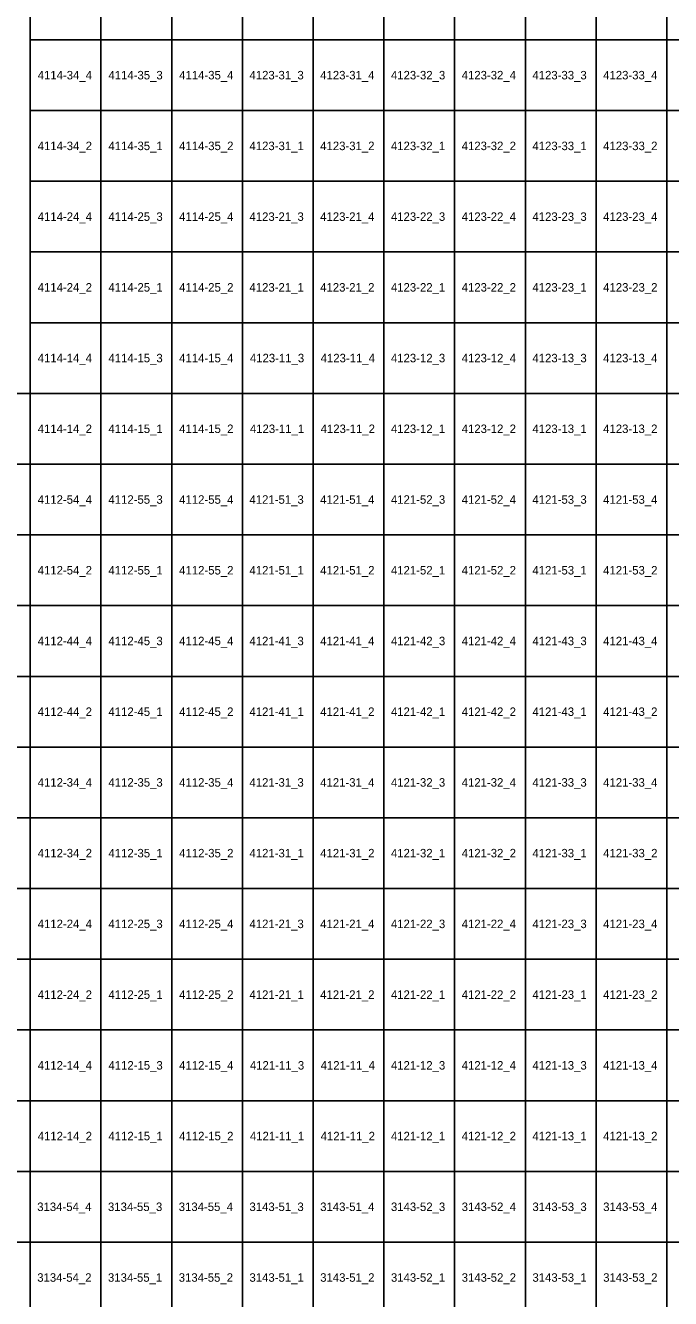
# Model space of a CAD drawing. Extents: x 312500 to 765000, y 172500 to 440000.
# Drawn here: x 342332 to 365129, y 295507 to 340507 of the extents above; entities that cross this region are included whole.
import ezdxf

# ---------------------------------------------------------------- set-up
doc = ezdxf.new("R2010")
doc.units = 0
doc.layers.add('Topo5_ramis_TKS2025', color=7, linetype='Continuous')
doc.layers.add('Topo5_ramis_TKS2025_Nr', color=7, linetype='Continuous')

msp = doc.modelspace()

# ---------------------------------------------------------------- linework, layer by layer
at = {"layer": 'Topo5_ramis_TKS2025'}
for points in [[(342500, 340000), (342500, 342500), (345000, 342500), (345000, 340000), (342500, 340000)], [(345000, 340000), (345000, 342500), (347500, 342500), (347500, 340000), (345000, 340000)], [(347500, 340000), (347500, 342500), (350000, 342500), (350000, 340000), (347500, 340000)], [(350000, 340000), (350000, 342500), (352500, 342500), (352500, 340000), (350000, 340000)], [(352500, 340000), (352500, 342500), (355000, 342500), (355000, 340000), (352500, 340000)], [(355000, 340000), (355000, 342500), (357500, 342500), (357500, 340000), (355000, 340000)], [(357500, 340000), (357500, 342500), (360000, 342500), (360000, 340000), (357500, 340000)], [(360000, 340000), (360000, 342500), (362500, 342500), (362500, 340000), (360000, 340000)], [(362500, 340000), (362500, 342500), (365000, 342500), (365000, 340000), (362500, 340000)], [(365000, 340000), (365000, 342500), (367500, 342500), (367500, 340000), (365000, 340000)], [(342500, 337500), (342500, 340000), (345000, 340000), (345000, 337500), (342500, 337500)], [(345000, 337500), (345000, 340000), (347500, 340000), (347500, 337500), (345000, 337500)], [(347500, 337500), (347500, 340000), (350000, 340000), (350000, 337500), (347500, 337500)], [(350000, 337500), (350000, 340000), (352500, 340000), (352500, 337500), (350000, 337500)], [(352500, 337500), (352500, 340000), (355000, 340000), (355000, 337500), (352500, 337500)], [(355000, 337500), (355000, 340000), (357500, 340000), (357500, 337500), (355000, 337500)], [(357500, 337500), (357500, 340000), (360000, 340000), (360000, 337500), (357500, 337500)], [(360000, 337500), (360000, 340000), (362500, 340000), (362500, 337500), (360000, 337500)], [(362500, 337500), (362500, 340000), (365000, 340000), (365000, 337500), (362500, 337500)], [(365000, 337500), (365000, 340000), (367500, 340000), (367500, 337500), (365000, 337500)], [(342500, 335000), (342500, 337500), (345000, 337500), (345000, 335000), (342500, 335000)], [(345000, 335000), (345000, 337500), (347500, 337500), (347500, 335000), (345000, 335000)], [(347500, 335000), (347500, 337500), (350000, 337500), (350000, 335000), (347500, 335000)], [(350000, 335000), (350000, 337500), (352500, 337500), (352500, 335000), (350000, 335000)], [(352500, 335000), (352500, 337500), (355000, 337500), (355000, 335000), (352500, 335000)], [(355000, 335000), (355000, 337500), (357500, 337500), (357500, 335000), (355000, 335000)], [(357500, 335000), (357500, 337500), (360000, 337500), (360000, 335000), (357500, 335000)], [(360000, 335000), (360000, 337500), (362500, 337500), (362500, 335000), (360000, 335000)], [(362500, 335000), (362500, 337500), (365000, 337500), (365000, 335000), (362500, 335000)], [(365000, 335000), (365000, 337500), (367500, 337500), (367500, 335000), (365000, 335000)], [(342500, 332500), (342500, 335000), (345000, 335000), (345000, 332500), (342500, 332500)], [(345000, 332500), (345000, 335000), (347500, 335000), (347500, 332500), (345000, 332500)], [(347500, 332500), (347500, 335000), (350000, 335000), (350000, 332500), (347500, 332500)], [(350000, 332500), (350000, 335000), (352500, 335000), (352500, 332500), (350000, 332500)], [(352500, 332500), (352500, 335000), (355000, 335000), (355000, 332500), (352500, 332500)], [(355000, 332500), (355000, 335000), (357500, 335000), (357500, 332500), (355000, 332500)], [(357500, 332500), (357500, 335000), (360000, 335000), (360000, 332500), (357500, 332500)], [(360000, 332500), (360000, 335000), (362500, 335000), (362500, 332500), (360000, 332500)], [(362500, 332500), (362500, 335000), (365000, 335000), (365000, 332500), (362500, 332500)], [(365000, 332500), (365000, 335000), (367500, 335000), (367500, 332500), (365000, 332500)], [(342500, 330000), (342500, 332500), (345000, 332500), (345000, 330000), (342500, 330000)], [(345000, 330000), (345000, 332500), (347500, 332500), (347500, 330000), (345000, 330000)], [(347500, 330000), (347500, 332500), (350000, 332500), (350000, 330000), (347500, 330000)], [(350000, 330000), (350000, 332500), (352500, 332500), (352500, 330000), (350000, 330000)], [(352500, 330000), (352500, 332500), (355000, 332500), (355000, 330000), (352500, 330000)], [(355000, 330000), (355000, 332500), (357500, 332500), (357500, 330000), (355000, 330000)], [(357500, 330000), (357500, 332500), (360000, 332500), (360000, 330000), (357500, 330000)], [(360000, 330000), (360000, 332500), (362500, 332500), (362500, 330000), (360000, 330000)], [(362500, 330000), (362500, 332500), (365000, 332500), (365000, 330000), (362500, 330000)], [(365000, 330000), (365000, 332500), (367500, 332500), (367500, 330000), (365000, 330000)], [(342500, 327500), (342500, 330000), (345000, 330000), (345000, 327500), (342500, 327500)], [(345000, 327500), (345000, 330000), (347500, 330000), (347500, 327500), (345000, 327500)], [(347500, 327500), (347500, 330000), (350000, 330000), (350000, 327500), (347500, 327500)], [(350000, 327500), (350000, 330000), (352500, 330000), (352500, 327500), (350000, 327500)], [(352500, 327500), (352500, 330000), (355000, 330000), (355000, 327500), (352500, 327500)], [(355000, 327500), (355000, 330000), (357500, 330000), (357500, 327500), (355000, 327500)], [(357500, 327500), (357500, 330000), (360000, 330000), (360000, 327500), (357500, 327500)], [(360000, 327500), (360000, 330000), (362500, 330000), (362500, 327500), (360000, 327500)], [(362500, 327500), (362500, 330000), (365000, 330000), (365000, 327500), (362500, 327500)], [(365000, 327500), (365000, 330000), (367500, 330000), (367500, 327500), (365000, 327500)], [(340000, 325000), (340000, 327500), (342500, 327500), (342500, 325000), (340000, 325000)], [(342500, 325000), (342500, 327500), (345000, 327500), (345000, 325000), (342500, 325000)], [(345000, 325000), (345000, 327500), (347500, 327500), (347500, 325000), (345000, 325000)], [(347500, 325000), (347500, 327500), (350000, 327500), (350000, 325000), (347500, 325000)], [(350000, 325000), (350000, 327500), (352500, 327500), (352500, 325000), (350000, 325000)], [(352500, 325000), (352500, 327500), (355000, 327500), (355000, 325000), (352500, 325000)], [(355000, 325000), (355000, 327500), (357500, 327500), (357500, 325000), (355000, 325000)], [(357500, 325000), (357500, 327500), (360000, 327500), (360000, 325000), (357500, 325000)], [(360000, 325000), (360000, 327500), (362500, 327500), (362500, 325000), (360000, 325000)], [(362500, 325000), (362500, 327500), (365000, 327500), (365000, 325000), (362500, 325000)], [(365000, 325000), (365000, 327500), (367500, 327500), (367500, 325000), (365000, 325000)], [(340000, 322500), (340000, 325000), (342500, 325000), (342500, 322500), (340000, 322500)], [(342500, 322500), (342500, 325000), (345000, 325000), (345000, 322500), (342500, 322500)], [(345000, 322500), (345000, 325000), (347500, 325000), (347500, 322500), (345000, 322500)], [(347500, 322500), (347500, 325000), (350000, 325000), (350000, 322500), (347500, 322500)], [(350000, 322500), (350000, 325000), (352500, 325000), (352500, 322500), (350000, 322500)], [(352500, 322500), (352500, 325000), (355000, 325000), (355000, 322500), (352500, 322500)], [(355000, 322500), (355000, 325000), (357500, 325000), (357500, 322500), (355000, 322500)], [(357500, 322500), (357500, 325000), (360000, 325000), (360000, 322500), (357500, 322500)], [(360000, 322500), (360000, 325000), (362500, 325000), (362500, 322500), (360000, 322500)], [(362500, 322500), (362500, 325000), (365000, 325000), (365000, 322500), (362500, 322500)], [(365000, 322500), (365000, 325000), (367500, 325000), (367500, 322500), (365000, 322500)], [(340000, 320000), (340000, 322500), (342500, 322500), (342500, 320000), (340000, 320000)], [(342500, 320000), (342500, 322500), (345000, 322500), (345000, 320000), (342500, 320000)], [(345000, 320000), (345000, 322500), (347500, 322500), (347500, 320000), (345000, 320000)], [(347500, 320000), (347500, 322500), (350000, 322500), (350000, 320000), (347500, 320000)], [(350000, 320000), (350000, 322500), (352500, 322500), (352500, 320000), (350000, 320000)], [(352500, 320000), (352500, 322500), (355000, 322500), (355000, 320000), (352500, 320000)], [(355000, 320000), (355000, 322500), (357500, 322500), (357500, 320000), (355000, 320000)], [(357500, 320000), (357500, 322500), (360000, 322500), (360000, 320000), (357500, 320000)], [(360000, 320000), (360000, 322500), (362500, 322500), (362500, 320000), (360000, 320000)], [(362500, 320000), (362500, 322500), (365000, 322500), (365000, 320000), (362500, 320000)], [(365000, 320000), (365000, 322500), (367500, 322500), (367500, 320000), (365000, 320000)], [(340000, 317500), (340000, 320000), (342500, 320000), (342500, 317500), (340000, 317500)], [(342500, 317500), (342500, 320000), (345000, 320000), (345000, 317500), (342500, 317500)], [(345000, 317500), (345000, 320000), (347500, 320000), (347500, 317500), (345000, 317500)], [(347500, 317500), (347500, 320000), (350000, 320000), (350000, 317500), (347500, 317500)], [(350000, 317500), (350000, 320000), (352500, 320000), (352500, 317500), (350000, 317500)], [(352500, 317500), (352500, 320000), (355000, 320000), (355000, 317500), (352500, 317500)], [(355000, 317500), (355000, 320000), (357500, 320000), (357500, 317500), (355000, 317500)], [(357500, 317500), (357500, 320000), (360000, 320000), (360000, 317500), (357500, 317500)], [(360000, 317500), (360000, 320000), (362500, 320000), (362500, 317500), (360000, 317500)], [(362500, 317500), (362500, 320000), (365000, 320000), (365000, 317500), (362500, 317500)], [(365000, 317500), (365000, 320000), (367500, 320000), (367500, 317500), (365000, 317500)], [(340000, 315000), (340000, 317500), (342500, 317500), (342500, 315000), (340000, 315000)], [(342500, 315000), (342500, 317500), (345000, 317500), (345000, 315000), (342500, 315000)], [(345000, 315000), (345000, 317500), (347500, 317500), (347500, 315000), (345000, 315000)], [(347500, 315000), (347500, 317500), (350000, 317500), (350000, 315000), (347500, 315000)], [(350000, 315000), (350000, 317500), (352500, 317500), (352500, 315000), (350000, 315000)], [(352500, 315000), (352500, 317500), (355000, 317500), (355000, 315000), (352500, 315000)], [(355000, 315000), (355000, 317500), (357500, 317500), (357500, 315000), (355000, 315000)], [(357500, 315000), (357500, 317500), (360000, 317500), (360000, 315000), (357500, 315000)], [(360000, 315000), (360000, 317500), (362500, 317500), (362500, 315000), (360000, 315000)], [(362500, 315000), (362500, 317500), (365000, 317500), (365000, 315000), (362500, 315000)], [(365000, 315000), (365000, 317500), (367500, 317500), (367500, 315000), (365000, 315000)], [(340000, 312500), (340000, 315000), (342500, 315000), (342500, 312500), (340000, 312500)], [(342500, 312500), (342500, 315000), (345000, 315000), (345000, 312500), (342500, 312500)], [(345000, 312500), (345000, 315000), (347500, 315000), (347500, 312500), (345000, 312500)], [(347500, 312500), (347500, 315000), (350000, 315000), (350000, 312500), (347500, 312500)], [(350000, 312500), (350000, 315000), (352500, 315000), (352500, 312500), (350000, 312500)], [(352500, 312500), (352500, 315000), (355000, 315000), (355000, 312500), (352500, 312500)], [(355000, 312500), (355000, 315000), (357500, 315000), (357500, 312500), (355000, 312500)], [(357500, 312500), (357500, 315000), (360000, 315000), (360000, 312500), (357500, 312500)], [(360000, 312500), (360000, 315000), (362500, 315000), (362500, 312500), (360000, 312500)], [(362500, 312500), (362500, 315000), (365000, 315000), (365000, 312500), (362500, 312500)], [(365000, 312500), (365000, 315000), (367500, 315000), (367500, 312500), (365000, 312500)], [(340000, 310000), (340000, 312500), (342500, 312500), (342500, 310000), (340000, 310000)], [(342500, 310000), (342500, 312500), (345000, 312500), (345000, 310000), (342500, 310000)], [(345000, 310000), (345000, 312500), (347500, 312500), (347500, 310000), (345000, 310000)], [(347500, 310000), (347500, 312500), (350000, 312500), (350000, 310000), (347500, 310000)], [(350000, 310000), (350000, 312500), (352500, 312500), (352500, 310000), (350000, 310000)], [(352500, 310000), (352500, 312500), (355000, 312500), (355000, 310000), (352500, 310000)], [(355000, 310000), (355000, 312500), (357500, 312500), (357500, 310000), (355000, 310000)], [(357500, 310000), (357500, 312500), (360000, 312500), (360000, 310000), (357500, 310000)], [(360000, 310000), (360000, 312500), (362500, 312500), (362500, 310000), (360000, 310000)], [(362500, 310000), (362500, 312500), (365000, 312500), (365000, 310000), (362500, 310000)], [(365000, 310000), (365000, 312500), (367500, 312500), (367500, 310000), (365000, 310000)], [(340000, 307500), (340000, 310000), (342500, 310000), (342500, 307500), (340000, 307500)], [(342500, 307500), (342500, 310000), (345000, 310000), (345000, 307500), (342500, 307500)], [(345000, 307500), (345000, 310000), (347500, 310000), (347500, 307500), (345000, 307500)], [(347500, 307500), (347500, 310000), (350000, 310000), (350000, 307500), (347500, 307500)], [(350000, 307500), (350000, 310000), (352500, 310000), (352500, 307500), (350000, 307500)], [(352500, 307500), (352500, 310000), (355000, 310000), (355000, 307500), (352500, 307500)], [(355000, 307500), (355000, 310000), (357500, 310000), (357500, 307500), (355000, 307500)], [(357500, 307500), (357500, 310000), (360000, 310000), (360000, 307500), (357500, 307500)], [(360000, 307500), (360000, 310000), (362500, 310000), (362500, 307500), (360000, 307500)], [(362500, 307500), (362500, 310000), (365000, 310000), (365000, 307500), (362500, 307500)], [(365000, 307500), (365000, 310000), (367500, 310000), (367500, 307500), (365000, 307500)], [(340000, 305000), (340000, 307500), (342500, 307500), (342500, 305000), (340000, 305000)], [(342500, 305000), (342500, 307500), (345000, 307500), (345000, 305000), (342500, 305000)], [(345000, 305000), (345000, 307500), (347500, 307500), (347500, 305000), (345000, 305000)], [(347500, 305000), (347500, 307500), (350000, 307500), (350000, 305000), (347500, 305000)], [(350000, 305000), (350000, 307500), (352500, 307500), (352500, 305000), (350000, 305000)], [(352500, 305000), (352500, 307500), (355000, 307500), (355000, 305000), (352500, 305000)], [(355000, 305000), (355000, 307500), (357500, 307500), (357500, 305000), (355000, 305000)], [(357500, 305000), (357500, 307500), (360000, 307500), (360000, 305000), (357500, 305000)], [(360000, 305000), (360000, 307500), (362500, 307500), (362500, 305000), (360000, 305000)], [(362500, 305000), (362500, 307500), (365000, 307500), (365000, 305000), (362500, 305000)], [(365000, 305000), (365000, 307500), (367500, 307500), (367500, 305000), (365000, 305000)], [(340000, 302500), (340000, 305000), (342500, 305000), (342500, 302500), (340000, 302500)], [(342500, 302500), (342500, 305000), (345000, 305000), (345000, 302500), (342500, 302500)], [(345000, 302500), (345000, 305000), (347500, 305000), (347500, 302500), (345000, 302500)], [(347500, 302500), (347500, 305000), (350000, 305000), (350000, 302500), (347500, 302500)], [(350000, 302500), (350000, 305000), (352500, 305000), (352500, 302500), (350000, 302500)], [(352500, 302500), (352500, 305000), (355000, 305000), (355000, 302500), (352500, 302500)], [(355000, 302500), (355000, 305000), (357500, 305000), (357500, 302500), (355000, 302500)], [(357500, 302500), (357500, 305000), (360000, 305000), (360000, 302500), (357500, 302500)], [(360000, 302500), (360000, 305000), (362500, 305000), (362500, 302500), (360000, 302500)], [(362500, 302500), (362500, 305000), (365000, 305000), (365000, 302500), (362500, 302500)], [(365000, 302500), (365000, 305000), (367500, 305000), (367500, 302500), (365000, 302500)], [(340000, 300000), (340000, 302500), (342500, 302500), (342500, 300000), (340000, 300000)], [(342500, 300000), (342500, 302500), (345000, 302500), (345000, 300000), (342500, 300000)], [(345000, 300000), (345000, 302500), (347500, 302500), (347500, 300000), (345000, 300000)], [(347500, 300000), (347500, 302500), (350000, 302500), (350000, 300000), (347500, 300000)], [(350000, 300000), (350000, 302500), (352500, 302500), (352500, 300000), (350000, 300000)], [(352500, 300000), (352500, 302500), (355000, 302500), (355000, 300000), (352500, 300000)], [(355000, 300000), (355000, 302500), (357500, 302500), (357500, 300000), (355000, 300000)], [(357500, 300000), (357500, 302500), (360000, 302500), (360000, 300000), (357500, 300000)], [(360000, 300000), (360000, 302500), (362500, 302500), (362500, 300000), (360000, 300000)], [(362500, 300000), (362500, 302500), (365000, 302500), (365000, 300000), (362500, 300000)], [(365000, 300000), (365000, 302500), (367500, 302500), (367500, 300000), (365000, 300000)], [(340000, 297500), (340000, 300000), (342500, 300000), (342500, 297500), (340000, 297500)], [(342500, 297500), (342500, 300000), (345000, 300000), (345000, 297500), (342500, 297500)], [(345000, 297500), (345000, 300000), (347500, 300000), (347500, 297500), (345000, 297500)], [(347500, 297500), (347500, 300000), (350000, 300000), (350000, 297500), (347500, 297500)], [(350000, 297500), (350000, 300000), (352500, 300000), (352500, 297500), (350000, 297500)], [(352500, 297500), (352500, 300000), (355000, 300000), (355000, 297500), (352500, 297500)], [(355000, 297500), (355000, 300000), (357500, 300000), (357500, 297500), (355000, 297500)], [(357500, 297500), (357500, 300000), (360000, 300000), (360000, 297500), (357500, 297500)], [(360000, 297500), (360000, 300000), (362500, 300000), (362500, 297500), (360000, 297500)], [(362500, 297500), (362500, 300000), (365000, 300000), (365000, 297500), (362500, 297500)], [(365000, 297500), (365000, 300000), (367500, 300000), (367500, 297500), (365000, 297500)], [(340000, 295000), (340000, 297500), (342500, 297500), (342500, 295000), (340000, 295000)], [(342500, 295000), (342500, 297500), (345000, 297500), (345000, 295000), (342500, 295000)], [(345000, 295000), (345000, 297500), (347500, 297500), (347500, 295000), (345000, 295000)], [(347500, 295000), (347500, 297500), (350000, 297500), (350000, 295000), (347500, 295000)], [(350000, 295000), (350000, 297500), (352500, 297500), (352500, 295000), (350000, 295000)], [(352500, 295000), (352500, 297500), (355000, 297500), (355000, 295000), (352500, 295000)], [(355000, 295000), (355000, 297500), (357500, 297500), (357500, 295000), (355000, 295000)], [(357500, 295000), (357500, 297500), (360000, 297500), (360000, 295000), (357500, 295000)], [(360000, 295000), (360000, 297500), (362500, 297500), (362500, 295000), (360000, 295000)], [(362500, 295000), (362500, 297500), (365000, 297500), (365000, 295000), (362500, 295000)], [(365000, 295000), (365000, 297500), (367500, 297500), (367500, 295000), (365000, 295000)]]:
    msp.add_lwpolyline(points, dxfattribs=at)

# ---------------------------------------------------------------- texts
at = {"layer": 'Topo5_ramis_TKS2025_Nr'}
for s, p in [('4114-34_4', (342764, 338600)), ('4114-35_3', (345264, 338600)), ('4114-35_4', (347764, 338600)), ('4123-31_3', (350248, 338600)), ('4123-31_4', (352748, 338600)), ('4123-32_3', (355248, 338600)), ('4123-32_4', (357748, 338600)), ('4123-33_3', (360248, 338600)), ('4123-33_4', (362748, 338600)), ('4114-34_2', (342764, 336100)), ('4114-35_1', (345264, 336100)), ('4114-35_2', (347764, 336100)), ('4123-31_1', (350248, 336100)), ('4123-31_2', (352748, 336100)), ('4123-32_1', (355248, 336100)), ('4123-32_2', (357748, 336100)), ('4123-33_1', (360248, 336100)), ('4123-33_2', (362748, 336100)), ('4114-24_4', (342764, 333600)), ('4114-25_3', (345264, 333600)), ('4114-25_4', (347764, 333600)), ('4123-21_3', (350248, 333600)), ('4123-21_4', (352748, 333600)), ('4123-22_3', (355248, 333600)), ('4123-22_4', (357748, 333600)), ('4123-23_3', (360248, 333600)), ('4123-23_4', (362748, 333600)), ('4114-24_2', (342764, 331100)), ('4114-25_1', (345264, 331100)), ('4114-25_2', (347764, 331100)), ('4123-21_1', (350248, 331100)), ('4123-21_2', (352748, 331100)), ('4123-22_1', (355248, 331100)), ('4123-22_2', (357748, 331100)), ('4123-23_1', (360248, 331100)), ('4123-23_2', (362748, 331100)), ('4114-14_4', (342764, 328600)), ('4114-15_3', (345264, 328600)), ('4114-15_4', (347764, 328600)), ('4123-11_3', (350264, 328600)), ('4123-11_4', (352764, 328600)), ('4123-12_3', (355248, 328600)), ('4123-12_4', (357748, 328600)), ('4123-13_3', (360248, 328600)), ('4123-13_4', (362748, 328600)), ('4114-14_2', (342764, 326100)), ('4114-15_1', (345264, 326100)), ('4114-15_2', (347764, 326100)), ('4123-11_1', (350264, 326100)), ('4123-11_2', (352764, 326100)), ('4123-12_1', (355248, 326100)), ('4123-12_2', (357748, 326100)), ('4123-13_1', (360248, 326100)), ('4123-13_2', (362748, 326100)), ('4112-54_4', (342764, 323600)), ('4112-55_3', (345264, 323600)), ('4112-55_4', (347764, 323600)), ('4121-51_3', (350248, 323600)), ('4121-51_4', (352748, 323600)), ('4121-52_3', (355248, 323600)), ('4121-52_4', (357748, 323600)), ('4121-53_3', (360248, 323600)), ('4121-53_4', (362748, 323600)), ('4112-54_2', (342764, 321100)), ('4112-55_1', (345264, 321100)), ('4112-55_2', (347764, 321100)), ('4121-51_1', (350248, 321100)), ('4121-51_2', (352748, 321100)), ('4121-52_1', (355248, 321100)), ('4121-52_2', (357748, 321100)), ('4121-53_1', (360248, 321100)), ('4121-53_2', (362748, 321100)), ('4112-44_4', (342764, 318600)), ('4112-45_3', (345264, 318600)), ('4112-45_4', (347764, 318600)), ('4121-41_3', (350248, 318600)), ('4121-41_4', (352748, 318600)), ('4121-42_3', (355248, 318600)), ('4121-42_4', (357748, 318600)), ('4121-43_3', (360248, 318600)), ('4121-43_4', (362748, 318600)), ('4112-44_2', (342764, 316100)), ('4112-45_1', (345264, 316100)), ('4112-45_2', (347764, 316100)), ('4121-41_1', (350248, 316100)), ('4121-41_2', (352748, 316100)), ('4121-42_1', (355248, 316100)), ('4121-42_2', (357748, 316100)), ('4121-43_1', (360248, 316100)), ('4121-43_2', (362748, 316100)), ('4112-34_4', (342764, 313600)), ('4112-35_3', (345264, 313600)), ('4112-35_4', (347764, 313600)), ('4121-31_3', (350248, 313600)), ('4121-31_4', (352748, 313600)), ('4121-32_3', (355248, 313600)), ('4121-32_4', (357748, 313600)), ('4121-33_3', (360248, 313600)), ('4121-33_4', (362748, 313600)), ('4112-34_2', (342764, 311100)), ('4112-35_1', (345264, 311100)), ('4112-35_2', (347764, 311100)), ('4121-31_1', (350248, 311100)), ('4121-31_2', (352748, 311100)), ('4121-32_1', (355248, 311100)), ('4121-32_2', (357748, 311100)), ('4121-33_1', (360248, 311100)), ('4121-33_2', (362748, 311100)), ('4112-24_4', (342764, 308600)), ('4112-25_3', (345264, 308600)), ('4112-25_4', (347764, 308600)), ('4121-21_3', (350248, 308600)), ('4121-21_4', (352748, 308600)), ('4121-22_3', (355248, 308600)), ('4121-22_4', (357748, 308600)), ('4121-23_3', (360248, 308600)), ('4121-23_4', (362748, 308600)), ('4112-24_2', (342764, 306100)), ('4112-25_1', (345264, 306100)), ('4112-25_2', (347764, 306100)), ('4121-21_1', (350248, 306100)), ('4121-21_2', (352748, 306100)), ('4121-22_1', (355248, 306100)), ('4121-22_2', (357748, 306100)), ('4121-23_1', (360248, 306100)), ('4121-23_2', (362748, 306100)), ('4112-14_4', (342764, 303600)), ('4112-15_3', (345264, 303600)), ('4112-15_4', (347764, 303600)), ('4121-11_3', (350264, 303600)), ('4121-11_4', (352764, 303600)), ('4121-12_3', (355248, 303600)), ('4121-12_4', (357748, 303600)), ('4121-13_3', (360248, 303600)), ('4121-13_4', (362748, 303600)), ('4112-14_2', (342764, 301100)), ('4112-15_1', (345264, 301100)), ('4112-15_2', (347764, 301100)), ('4121-11_1', (350264, 301100)), ('4121-11_2', (352764, 301100)), ('4121-12_1', (355248, 301100)), ('4121-12_2', (357748, 301100)), ('4121-13_1', (360248, 301100)), ('4121-13_2', (362748, 301100)), ('3134-54_4', (342748, 298600)), ('3134-55_3', (345248, 298600)), ('3134-55_4', (347748, 298600)), ('3143-51_3', (350248, 298600)), ('3143-51_4', (352748, 298600)), ('3143-52_3', (355248, 298600)), ('3143-52_4', (357748, 298600)), ('3143-53_3', (360248, 298600)), ('3143-53_4', (362748, 298600)), ('3134-54_2', (342748, 296100)), ('3134-55_1', (345248, 296100)), ('3134-55_2', (347748, 296100)), ('3143-51_1', (350248, 296100)), ('3143-51_2', (352748, 296100)), ('3143-52_1', (355248, 296100)), ('3143-52_2', (357748, 296100)), ('3143-53_1', (360248, 296100)), ('3143-53_2', (362748, 296100))]:
    msp.add_text(s, height=300, dxfattribs=at).set_placement(p)

doc.saveas('drawing.dxf')
